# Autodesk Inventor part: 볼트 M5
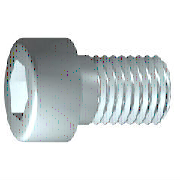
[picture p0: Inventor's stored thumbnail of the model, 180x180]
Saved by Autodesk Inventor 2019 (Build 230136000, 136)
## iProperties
IsCustomPart: 1
Created: 2012-02
Part Number: 볼트 M5
Material: 강철, 연강
Description: 6각머리 태핑 나사
Document SubType Name: Modeling
Standard: KS B 1003
Designer: mduedu
Standards Organization: KS
Language: ko-KR
Size Designation: M 5 x 16
Categories: <MemberInstance><Categories><Category DisplayName="조임쇠" InternalName="e4da775c-781d-43d5-af7c-5136215cf5a6" Mnemonic="FSTN"><Category DisplayName="볼트" InternalN
Density: 1 g/cm^3
Appearance: 강철
Author: mduedu
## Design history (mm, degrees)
sketch "스케치1"
  geometry: L1 (-1.167, 0)-(16, 0); L2 (16, 0)-(16, 2.5); L3 (16, 2.5)-(2, 2.5); L4 (2, 2.5)-(1.509, 2.5); L5 (1.509, 2.5)-(0, 2.5); L6 (0, 2.5)-(0, 4.25); L7 (0, 4.25)-(-5, 4.25); L8 (-5, 4.25)-(-5, 2.309); L9 (-5, 2.309)-(-2.5, 2.309); L10 (-2.5, 2.309)-(-1.167, 0); L11 (-9.2, 0)-(20.2, 0) reference; L12 (0, -0.85)-(0, 5.1) reference; L13 (2, 2.5)-(0, 2.5)
  constraints: 22 end point, 6 parallel, 2 collinear, 2 perpendicular, 1 horizontal, 1 point on line
  dimensions: "d1" = 14 distance from line of L3.end L2 (= GEL); "d2" = 0.49086 distance of L4.end L3.end (computed from GAL); "d3" = 5 distance between parallel lines of L8 L6 (= KOH); "d4" = 2.5 distance of L8.end L9.end (= INTI); "d5" = 60 deg angle of L10 L1; "d6" = 5 diameter of L3 L1 (= GD); "d7" = 5 diameter of L5 L1 (= BDM); "d8" = 4.6188 diameter of L9 L1 (= 1.1547 x SW); "d9" = 8.5 diameter of L7 L1 (= KOD); "d26" = 16 distance between parallel lines of L12 L2 (= NLG)
revolve "본체" sketch "스케치1" stored, may be unused: angle "d10" = 90 deg
sketch "스케치2"
  geometry: L1 (0, -5.95)-(0, 5.95) reference; L2 (-5.95, 0)-(5.95, 0) reference; L3 (2.309, 0)-(1.155, -2); L4 (1.155, -2)-(-1.155, -2); L5 (-1.155, -2)-(-2.309, 0); L6 (-2.309, 0)-(-1.155, 2); L7 (-1.155, 2)-(1.155, 2); L8 (1.155, 2)-(2.309, 0); 2 further points
  constraints: 12 end point, 1 coincident, 1 horizontal alignment, 1 point on line, 12 other
extrude "슬롯" join sketch "스케치2" stored distance "d11" = 10; taper "d12" = 0 deg
workplane "Work Plane1"
fillet "Fillet2" dims "d30" = 0.1 (= R)
body "Solid1"
fillet "모깎기1" dims "d17" = 0.5 (= RR)
feature "스레드" dims "d13" = 14 (= GEL), "d14" = 0
chamfer "모따기1" distance "d15" = 0.49076 (= -0.5 x SPD + 0.5 x GD); stored, may be unused: second distance "d16" = 0.49076 (= GUL), angle "d27" = 45 deg
other parameters: "GD" = 5 (= NND) [user parameter; used in 2 equation terms], "NLG" = 16 [user parameter; used in 1 equation term], "GEL" = 14 [user parameter; used in 2 equation terms], "KOD" = 8.5 [user parameter; used in 1 equation term], "KOH" = 5 [user parameter; used in 1 equation term], "INTI" = 2.5 [user parameter; used in 1 equation term], "GAL" = 0.49076 (= 0.61345 x PTC) [user parameter; used in 1 equation term], "GUL" = 0.49076 (= 0.61345 x PTC) [user parameter; used in 1 equation term], "BDM" = 5 (= NND) [user parameter; used in 1 equation term], "SW" = 4 [user parameter; used in 2 equation terms], "RR" = 0.5 [user parameter; used in 1 equation term], "SPD" = 4.01848 (= NND - 1.2269 x PTC) [user parameter; used in 1 equation term], "d19" = 0, "d28" = 0, "d29" = 0, "R" = 0.1 [user parameter; used in 1 equation term], "PHH" = 0.2 [user parameter], "GD1" = 4.01848 (= THREADDIA - 1.2269 x PTC) [user parameter], "THREADDIA" = 5 [user parameter; used in 1 equation term], "FAWI" = 45 deg [user parameter], "TPU" = 12.5 (computed from PTC) [user parameter], "PTC" = 0.8 [user parameter; used in 5 equation terms], "NND" = 5 [user parameter; used in 3 equation terms], "TOA" = 30 deg [user parameter], "E0" = 4.62 (= 1.155 x SW) [user parameter]
